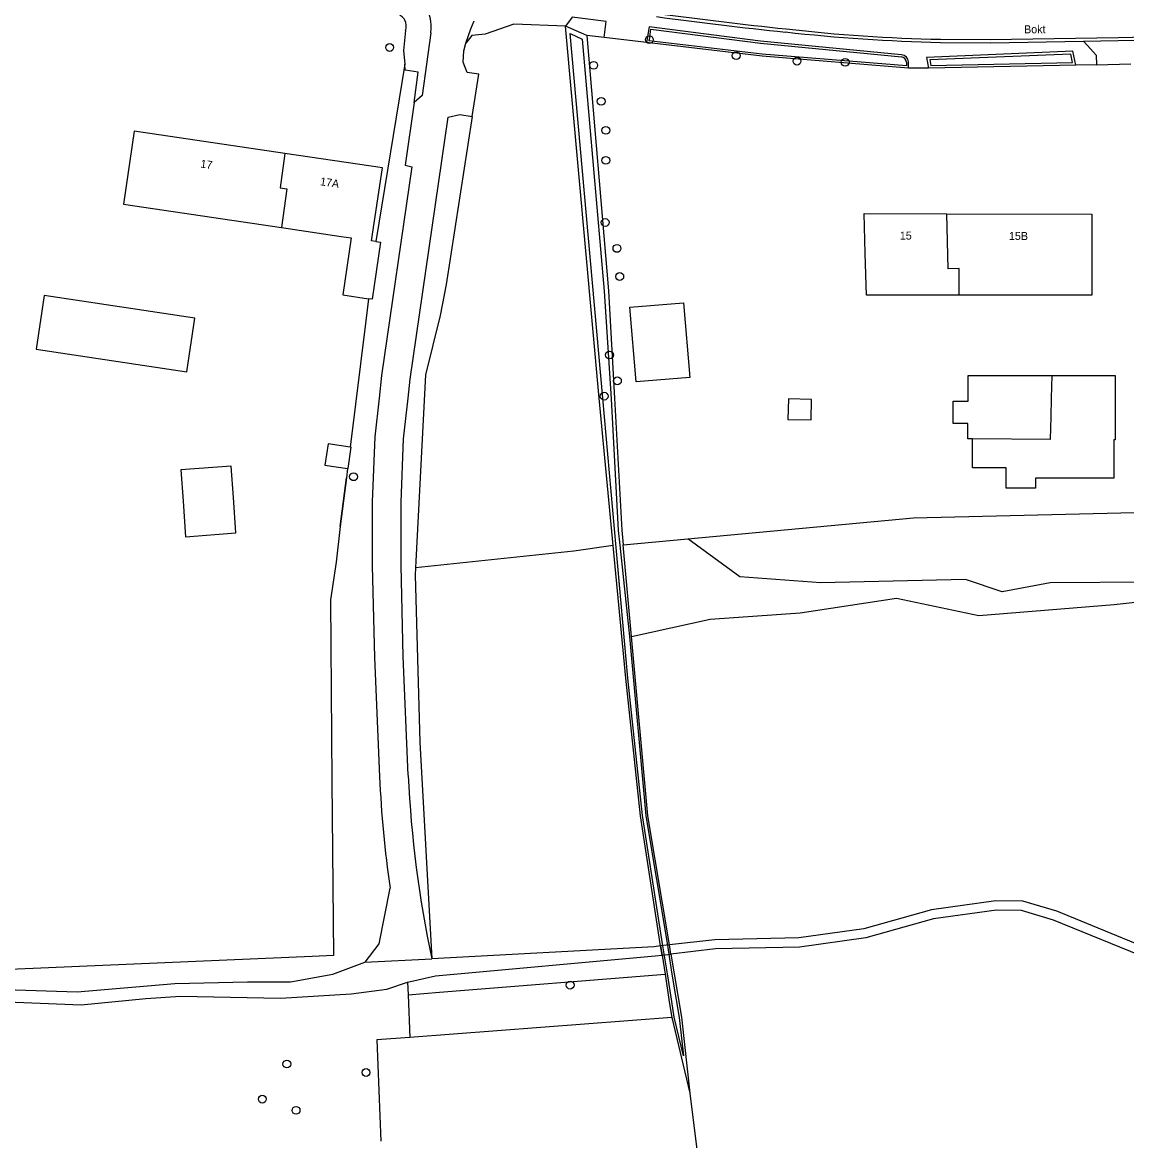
# Model space of a CAD drawing. Extents: x 162515 to 163909, y 388494 to 389773.
# Drawn here: x 162630.7 to 162768.7, y 388907.2 to 389047 of the extents above; entities that cross this region are included whole.
import ezdxf

# ---------------------------------------------------------------- set-up
doc = ezdxf.new("R2010")
doc.units = 0
for name, color, linetype in [('IMGEO_Boom', 7, 'Continuous'), ('IMGEO_Erf', 7, 'Continuous'), ('IMGEO_Grasland_agrarisch', 7, 'Continuous'), ('IMGEO_Grasland_overig', 7, 'Continuous'), ('IMGEO_Groenvoorziening', 7, 'Continuous'), ('IMGEO_Hek', 7, 'Continuous'), ('IMGEO_Loofbos', 7, 'Continuous'), ('IMGEO_Openbare_ruimte_label', 7, 'Continuous'), ('IMGEO_Pand', 7, 'Continuous'), ('IMGEO_Pand_nummerreeks', 7, 'Continuous'), ('IMGEO_Rijbaan_lokaal_gesloten', 7, 'Continuous'), ('IMGEO_Rijbaan_lokaal_halfverhard', 7, 'Continuous'), ('IMGEO_Rijbaan_lokaal_onverhard', 7, 'Continuous'), ('IMGEO_Voetpad_halfverhard', 7, 'Continuous'), ('IMGEO_Waterloop', 7, 'Continuous')]:
    doc.layers.add(name, color=color, linetype=linetype)

msp = doc.modelspace()

# ---------------------------------------------------------------- linework, layer by layer
at = {"layer": 'IMGEO_Boom'}
for centre in [(162709.08, 389044.8), (162676.63, 389043.83), (162719.93, 389042.81), (162702.13, 389041.6), (162727.53, 389042.12), (162733.55, 389041.97), (162703.06, 389037.09), (162703.65, 389033.47), (162703.64, 389029.72), (162703.56, 389021.96), (162705.03, 389018.72), (162705.38, 389015.21), (162704.1, 389005.4), (162705.09, 389002.17), (162703.44, 389000.25), (162672.12, 388990.19), (162699.18, 388926.67), (162663.79, 388916.81), (162673.68, 388915.75), (162660.72, 388912.42), (162664.94, 388911.02)]:
    msp.add_circle(centre, 0.489, dxfattribs=at)
at = {"layer": 'IMGEO_Erf'}
for points in [[(162704.58, 388981.58), (162702.83, 389000), (162698.61, 389046.48)], [(162701.26, 389045.33), (162703.97, 389013.41), (162704.72, 389000), (162705.65, 388983.52), (162705.82, 388981.68)], [(162741.47, 389041.26), (162723.17, 389042.73), (162708.72, 389044.45)], [(162762.37, 389041.61), (162743.97, 389041.23)]]:
    msp.add_lwpolyline(points, dxfattribs=at)
at = {"layer": 'IMGEO_Grasland_agrarisch'}
for points in [[(162704.58, 388981.58), (162699.64, 388980.89), (162679.87, 388978.79)], [(162710.49, 388931.57), (162707.98, 388947.83), (162706.16, 388965), (162704.58, 388981.58)]]:
    msp.add_lwpolyline(points, dxfattribs=at)
at = {"layer": 'IMGEO_Grasland_overig'}
for points in [[(162686.95, 389035.21), (162683.69, 389014.23), (162682.95, 389010.32), (162681.09, 389002.93), (162679.91, 388979.62), (162679.87, 388978.79)], [(162705.82, 388981.68), (162713.87, 388982.43)], [(162771.63, 388977.03), (162759.18, 388976.94), (162753.18, 388975.82), (162748.59, 388977.36), (162730.5, 388976.95), (162720.37, 388977.67), (162713.87, 388982.43)], [(162706.86, 388970.23), (162705.82, 388981.68)], [(162679.87, 388978.79), (162679.83, 388977.88), (162680.42, 388957.01), (162681.91, 388929.94)], [(162711.04, 388928.02), (162711.57, 388924.58), (162711.87, 388922.6)], [(162711.87, 388922.6), (162679.15, 388920.12)]]:
    msp.add_lwpolyline(points, dxfattribs=at)
at = {"layer": 'IMGEO_Groenvoorziening'}
for points in [[(162698.61, 389046.48), (162692.16, 389046.72), (162688.55, 389045.49), (162686.9, 389045.33), (162686.13, 389044.35)], [(162740.6, 389042.91), (162722.98, 389044.63), (162709.07, 389046.4), (162708.72, 389044.45)], [(162678.63, 389045.93), (162678.36, 389043.46), (162678.51, 389041.74)], [(162708.72, 389044.45), (162703.43, 389045.08)], [(162762.37, 389041.61), (162762, 389043.35), (162743.73, 389042.59), (162743.97, 389041.23)], [(162741.47, 389041.26), (162741.46, 389042.02)], [(162678.51, 389041.74), (162674.91, 389019.57)], [(162679.69, 389036.94), (162680.18, 389040.72), (162678.57, 389040.99), (162678.51, 389041.74)], [(162743.97, 389041.23), (162741.47, 389041.26)], [(162764.94, 389041.67), (162762.37, 389041.61)], [(162674, 389012.43), (162673.66, 389009.65), (162671.71, 388993.89)], [(162671.38, 388991.23), (162671.23, 388990.04), (162670.45, 388983.96), (162669.94, 388979.5), (162669.22, 388974.79), (162669.42, 388952.14), (162669.61, 388930.37), (162666.94, 388930.26), (162614.58, 388927.98), (162598.17, 388927.27)], [(162713.87, 388982.43), (162742.1, 388985.07), (162771.44, 388985.76)], [(162711.87, 388922.6), (162714.16, 388913.17)]]:
    msp.add_lwpolyline(points, dxfattribs=at)
for centre, radius, start, end in [((162677.11, 389046.47), 1.61, 340.2541, 77.4819), ((162740.51, 389041.96), 0.955, 3.6142, 84.3549)]:
    msp.add_arc(centre, radius, start, end, dxfattribs=at)
at = {"layer": 'IMGEO_Hek'}
for points in [[(162670.45, 388983.96), (162671.23, 388990.04)], [(162669.94, 388979.5), (162669.22, 388974.79), (162669.42, 388952.14)], [(162669.42, 388952.14), (162669.61, 388930.37), (162666.94, 388930.26)], [(162666.94, 388930.26), (162614.58, 388927.98)], [(162682.87, 388925.77), (162711.04, 388928.02)], [(162678.93, 388925.46), (162682.87, 388925.77)]]:
    msp.add_lwpolyline(points, dxfattribs=at)
at = {"layer": 'IMGEO_Loofbos'}
for points in [[(162706.86, 388970.23), (162716.69, 388972.41), (162727.93, 388973.18), (162739.95, 388975), (162750.24, 388972.84), (162767.18, 388974.22), (162771.68, 388974.74)], [(162711.59, 388931.69), (162708.89, 388947.83), (162706.86, 388970.23)], [(162710.67, 388930.42), (162711.04, 388928.02)], [(162711.78, 388930.55), (162712.19, 388928.08), (162713.1, 388922.66), (162713.16, 388922.29), (162714.16, 388913.17)], [(162678.93, 388925.46), (162682.87, 388925.77), (162711.04, 388928.02)], [(162678.87, 388927.02), (162678.93, 388925.46)], [(162678.93, 388925.46), (162679.15, 388920.12)], [(162679.15, 388920.12), (162675.02, 388919.81), (162675.53, 388907.17)], [(162714.16, 388913.17), (162720.77, 388860.13)]]:
    msp.add_lwpolyline(points, dxfattribs=at)
at = {"layer": 'IMGEO_Pand'}
for points in [[(162663.55, 389030.58), (162644.71, 389033.37), (162643.36, 389024.24), (162663.1, 389021.32)], [(162663.55, 389030.58), (162662.94, 389026.3), (162663.8, 389026.17), (162663.1, 389021.32)], [(162674.91, 389019.57), (162674.38, 389019.65), (162675.73, 389028.77), (162663.55, 389030.58)], [(162747.8, 389012.87), (162736.21, 389012.87), (162736.06, 389018.09), (162735.92, 389023.09), (162746.26, 389023.06)], [(162747.8, 389012.87), (162747.81, 389016.22), (162746.43, 389016.18), (162746.26, 389023.06)], [(162746.26, 389023.06), (162764.35, 389023.01), (162764.37, 389018.01), (162764.39, 389012.86), (162747.8, 389012.87)], [(162663.1, 389021.32), (162670.57, 389020.21), (162671.81, 389020.03), (162670.77, 389012.9), (162674, 389012.43)], [(162674.91, 389019.57), (162675.47, 389019.49), (162674.43, 389012.36), (162674, 389012.43)], [(162651.27, 389003.29), (162652.27, 389010.01), (162633.47, 389012.82), (162632.47, 389006.11), (162651.27, 389003.29)], [(162713.34, 389011.92), (162714.12, 389002.59), (162707.43, 389002.03), (162706.65, 389011.36), (162713.34, 389011.92)], [(162749.46, 388994.92), (162748.86, 388994.93), (162748.86, 388996.83), (162747.05, 388996.83), (162747.05, 388999.63), (162748.9, 388999.62), (162748.9, 389000), (162748.91, 389002.85), (162759.37, 389002.84)], [(162759.37, 389002.84), (162759.3, 389000), (162759.25, 388997.67), (162759.18, 388994.83), (162749.46, 388994.92)], [(162759.37, 389002.84), (162767.29, 389002.84), (162767.29, 389000), (162767.28, 388994.8), (162767.11, 388994.8), (162767.11, 388990.02), (162757.34, 388990.02), (162757.34, 388988.78), (162753.67, 388988.78), (162753.67, 388991.31), (162749.46, 388991.32), (162749.46, 388994.92)], [(162726.4, 388997.34), (162729.3, 388997.29), (162729.35, 388999.85), (162726.45, 388999.91), (162726.4, 388997.34)], [(162671.71, 388993.89), (162668.93, 388994.29), (162668.55, 388991.63), (162671.38, 388991.23)], [(162671.38, 388991.23), (162671.45, 388991.22), (162671.83, 388993.87), (162671.71, 388993.89)], [(162656.81, 388991.5), (162650.53, 388991.04), (162650.81, 388987.15), (162651.14, 388982.7), (162657.42, 388983.16), (162657.1, 388987.61), (162656.81, 388991.5)]]:
    msp.add_lwpolyline(points, dxfattribs=at)
at = {"layer": 'IMGEO_Rijbaan_lokaal_gesloten'}
for points in [[(162745.45, 389044.85), (162751.67, 389044.82), (162767.65, 389045.08), (162778.41, 389045.32)], [(162711.59, 388931.69), (162710.49, 388931.57), (162710.67, 388930.42), (162711.78, 388930.55), (162711.59, 388931.69)]]:
    msp.add_lwpolyline(points, dxfattribs=at)
for centre, radius, start, end in [((162795.11, 389689.92), 647.46, 262.44713, 263.88718), ((162749.34, 389247.24), 202.42, 263.4277, 268.9)]:
    msp.add_arc(centre, radius, start, end, dxfattribs=at)
at = {"layer": 'IMGEO_Rijbaan_lokaal_halfverhard'}
for points in [[(162763.31, 389044.61), (162767.65, 389044.69), (162770.28, 389044.75)], [(162745.47, 389044.46), (162751.7, 389044.41), (162763.31, 389044.61)], [(162780.17, 388928.65), (162774.27, 388930.05), (162759.98, 388935.89), (162755.76, 388937.15), (162752.38, 388937.21), (162744.35, 388936.06), (162735.9, 388933.72), (162727.74, 388932.58), (162717.28, 388932.34), (162711.59, 388931.69)], [(162780.35, 388927.41), (162773.92, 388928.95), (162759.59, 388934.8), (162755.59, 388936), (162752.45, 388936.05), (162744.59, 388934.93), (162736.14, 388932.59), (162727.84, 388931.42), (162717.36, 388931.19), (162711.78, 388930.55)], [(162711.78, 388930.55), (162711.59, 388931.69)]]:
    msp.add_lwpolyline(points, dxfattribs=at)
for centre, radius, start, end in [((162768.78, 389469.71), 426.1, 262.0684, 264.2522), ((162750.45, 389264.13), 219.72, 263.6397, 268.7019)]:
    msp.add_arc(centre, radius, start, end, dxfattribs=at)
at = {"layer": 'IMGEO_Rijbaan_lokaal_onverhard'}
for points in [[(162686.13, 389044.35), (162686.76, 389046.15), (162687.19, 389047.16)], [(162681.77, 389045.67), (162680.7, 389037.81), (162679.69, 389036.94)], [(162686.95, 389035.21), (162687.77, 389040.48), (162686.33, 389040.71), (162685.83, 389042.01), (162685.88, 389043.41), (162686.13, 389044.35)], [(162679.69, 389036.94), (162678.56, 389029.1), (162679.41, 389028.93), (162675.62, 389002.84), (162675.31, 389000), (162674.78, 388995.18), (162674.45, 388987.07), (162674.46, 388979.04), (162674.72, 388967.62), (162675.36, 388952.72)], [(162678.96, 388952.88), (162678.32, 388967.74), (162678.07, 388979.08), (162678.05, 388987), (162678.37, 388994.91), (162678.93, 389000), (162679.2, 389002.39), (162683.94, 389035.1), (162685.42, 389035.44), (162686.95, 389035.21)], [(162676.67, 388938.79), (162675.3, 388931.84), (162673.53, 388929.52)], [(162710.49, 388931.57), (162709.68, 388931.47), (162681.91, 388929.94)], [(162710.67, 388930.42), (162710.49, 388931.57)], [(162678.87, 388927.02), (162682.38, 388927.84), (162709.8, 388930.32), (162710.67, 388930.42)], [(162598.22, 388926.18), (162600.93, 388926.51), (162616.81, 388927.16), (162620.85, 388926.35), (162637.57, 388925.81), (162649.8, 388926.85), (162658.85, 388927.06), (162664.24, 388927.09), (162669.52, 388928.04), (162673.53, 388929.52)], [(162673.53, 388929.52), (162681.91, 388929.94)], [(162624.73, 388924.76), (162638.07, 388924.19), (162646.15, 388924.99), (162650.5, 388925.3), (162662.99, 388925.04), (162671.81, 388925.58), (162676.3, 388926.18), (162678.87, 388927.02)]]:
    msp.add_lwpolyline(points, dxfattribs=at)
for centre, radius, start, end in [((162676.32, 389046.41), 5.5, 352.2, 70.4415), ((162817.7, 388959.04), 142.47, 182.544, 188.1712), ((162817.58, 388959.03), 138.76, 182.5435, 192.1018)]:
    msp.add_arc(centre, radius, start, end, dxfattribs=at)
at = {"layer": 'IMGEO_Voetpad_halfverhard'}
for points in [[(162763.31, 389044.61), (162764.22, 389043.66), (162764.91, 389042.85), (162764.94, 389041.67)], [(162764.94, 389041.67), (162769.26, 389041.78)]]:
    msp.add_lwpolyline(points, dxfattribs=at)
at = {"layer": 'IMGEO_Waterloop'}
for points in [[(162703.43, 389045.08), (162703.67, 389047.09), (162699.45, 389047.63), (162698.61, 389046.48)], [(162701.26, 389045.33), (162698.61, 389046.48)], [(162741.21, 389042), (162741.21, 389041.54), (162723.19, 389042.99), (162709.02, 389044.67), (162709.08, 389044.8), (162709.28, 389046.12), (162722.95, 389044.38), (162740.57, 389042.66)], [(162711.3, 388931.91), (162711.89, 388928.03), (162712.79, 388922.61), (162712.86, 388922.24), (162713.34, 388917.85), (162712.17, 388922.65), (162711.87, 388924.63), (162711.35, 388928.07), (162710.71, 388931.84), (162708.23, 388947.87), (162706.41, 388965.03), (162703.27, 388999.99), (162699.2, 389045.57), (162700.69, 389044.87), (162703.45, 389013.38), (162704.29, 388999.94), (162705.19, 388983.48), (162705.41, 388981.63), (162706.61, 388970.21), (162708.64, 388947.8), (162711.3, 388931.91)], [(162703.43, 389045.08), (162701.26, 389045.33)], [(162761.73, 389043), (162744.12, 389042.27), (162744.25, 389041.57), (162761.96, 389041.94), (162761.73, 389043)]]:
    msp.add_lwpolyline(points, dxfattribs=at)
msp.add_arc((162740.51, 389041.96), 0.698, 3.2624, 85.1436, dxfattribs=at)

# ---------------------------------------------------------------- texts
at = {"layer": 'IMGEO_Openbare_ruimte_label'}
msp.add_text('Bokt', height=1, rotation=0.5156, dxfattribs=at).set_placement((162755.91, 389045.59))
at = {"layer": 'IMGEO_Pand_nummerreeks'}
for s, rotation, p in [('17', 351.6263, (162652.94, 389028.84)), ('17A', 351.5234, (162667.89, 389026.62)), ('15', 0.0671, (162740.38, 389019.82)), ('15B', 359.7086, (162754.01, 389019.78))]:
    msp.add_text(s, height=1, rotation=rotation, dxfattribs=at).set_placement(p)

doc.saveas('drawing.dxf')
